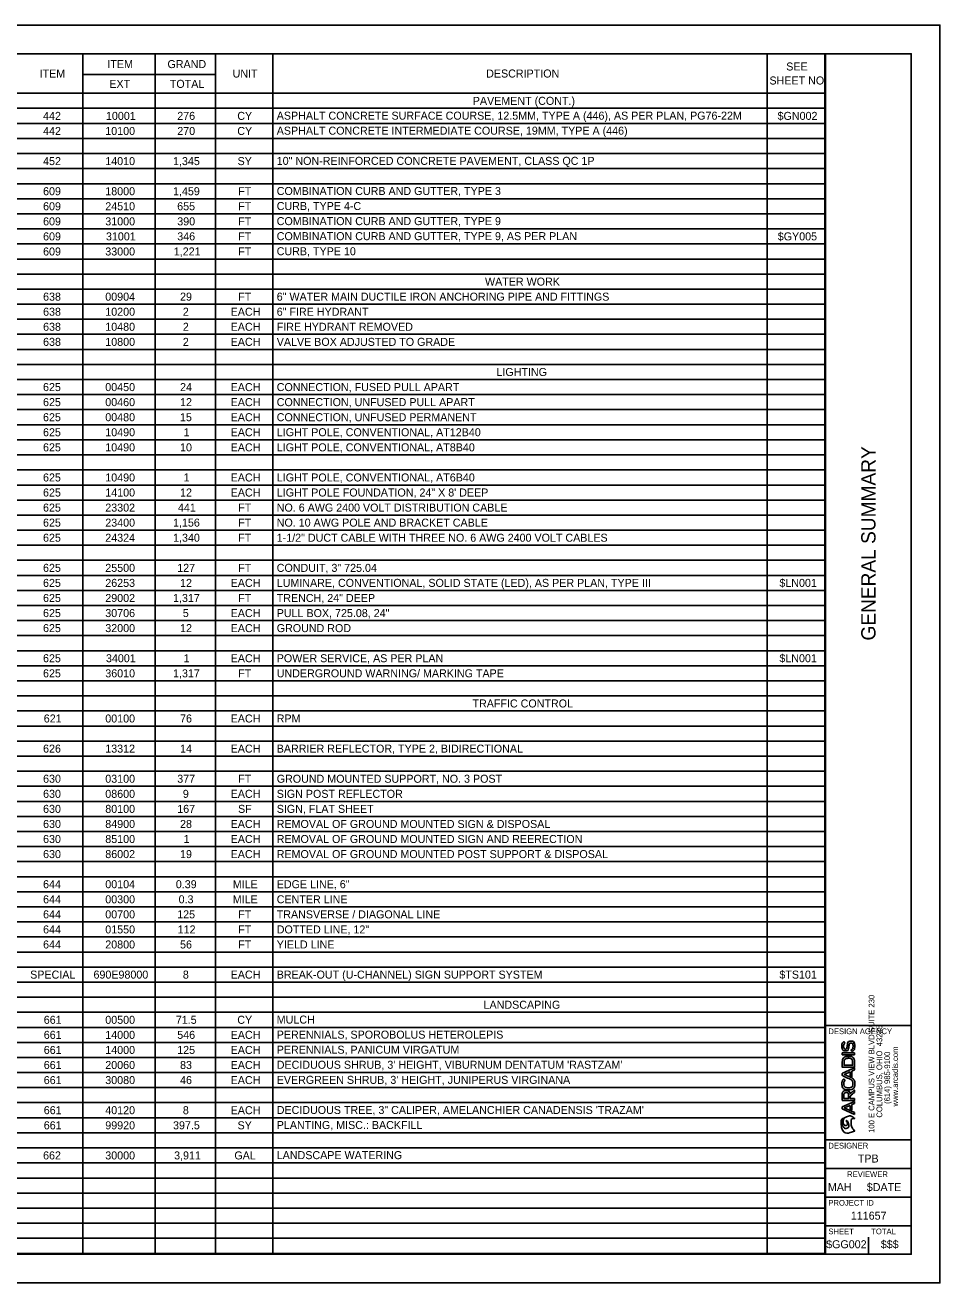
# Model space of a CAD drawing. Extents: x 0 to 34, y 0 to 22.
# Drawn here: x 18 to 34, y 0 to 22 of the extents above; entities that cross this region are included whole.
import ezdxf

# ---------------------------------------------------------------- set-up
doc = ezdxf.new("R2010")
doc.units = 0
for name, color, linetype in [('SH_Border', 7, 'Continuous'), ('SH_Cut_Line', 7, 'Continuous'), ('SH_Data', 7, 'Continuous'), ('SH_Text', 7, 'Continuous')]:
    doc.layers.add(name, color=color, linetype=linetype)

msp = doc.modelspace()

# ---------------------------------------------------------------- linework, layer by layer
at = {"layer": 'SH_Border'}
for p, q in [((32, 0.5), (32, 21.5)), ((32, 4.5), (33.5, 4.5)), ((32, 2.5), (33.5, 2.5)), ((32, 2), (33.5, 2)), ((32, 1.5), (33.5, 1.5)), ((32, 1), (33.5, 1))]:
    msp.add_line(p, q, dxfattribs=at)
msp.add_lwpolyline([(1.5, 21.5), (33.5, 21.5), (33.5, 0.5), (1.5, 0.5)], close=True, dxfattribs=at)
at = {"layer": 'SH_Cut_Line'}
msp.add_lwpolyline([(0, 0), (34, 0), (34, 22), (0, 22)], close=True, dxfattribs=at)
at = {"layer": 'SH_Data'}
for p, q in [((32.507, 4.022), (32.292, 4.022)), ((32.292, 4.022), (32.292, 3.988)), ((32.292, 3.988), (32.507, 3.988)), ((32.507, 3.988), (32.507, 4.022)), ((32.75, 3.5), (32.75, 3.5)), ((32.75, 3.5), (32.75, 3.5)), ((32.507, 3.175), (32.292, 3.079)), ((32.328, 3.06), (32.431, 3.105)), ((32.431, 3.105), (32.431, 3.034)), ((32.462, 3.119), (32.507, 3.139)), ((32.462, 3.02), (32.462, 3.119)), ((32.507, 3.139), (32.507, 3.175)), ((32.292, 3.079), (32.292, 3.041)), ((32.292, 3.041), (32.507, 2.945)), ((32.507, 2.981), (32.328, 3.06)), ((32.431, 3.034), (32.462, 3.02)), ((32.507, 2.945), (32.507, 2.981)), ((32.375, 0.675), (32.375, 0.675)), ((32.75, 0.5), (32.75, 0.8))]:
    msp.add_line(p, q, dxfattribs=at)
for points, degree in [([(32.34, 4.193), (32.325, 4.183), (32.316, 4.163), (32.316, 4.14), (32.316, 4.111), (32.328, 4.09), (32.348, 4.09), (32.369, 4.09), (32.375, 4.114), (32.379, 4.143), (32.385, 4.187), (32.398, 4.229), (32.446, 4.229), (32.494, 4.229), (32.512, 4.185), (32.512, 4.14), (32.512, 4.099), (32.5, 4.067), (32.463, 4.047), (32.463, 4.047), (32.446, 4.073), (32.446, 4.073), (32.472, 4.088), (32.482, 4.115), (32.482, 4.14), (32.482, 4.166), (32.473, 4.195), (32.446, 4.195), (32.422, 4.195), (32.414, 4.17), (32.41, 4.14), (32.405, 4.097), (32.394, 4.056), (32.348, 4.056), (32.303, 4.056), (32.286, 4.1), (32.286, 4.139), (32.286, 4.17), (32.293, 4.201), (32.322, 4.22), (32.322, 4.22), (32.34, 4.193), (32.34, 4.193), (32.34, 4.193), (32.34, 4.193), (32.34, 4.193)], 3), ([(32.292, 3.772), (32.292, 3.772), (32.507, 3.772), (32.507, 3.772), (32.507, 3.772), (32.507, 3.854), (32.507, 3.854), (32.507, 3.929), (32.452, 3.963), (32.398, 3.962), (32.345, 3.961), (32.292, 3.927), (32.292, 3.854)], 3), ([(32.292, 3.664), (32.292, 3.664), (32.292, 3.626), (32.292, 3.626), (32.292, 3.626), (32.432, 3.563), (32.432, 3.563), (32.432, 3.563), (32.432, 3.563), (32.432, 3.563), (32.445, 3.557), (32.453, 3.549), (32.456, 3.547), (32.471, 3.532), (32.479, 3.51), (32.479, 3.49), (32.479, 3.434), (32.44, 3.411), (32.401, 3.41), (32.361, 3.41), (32.321, 3.435), (32.321, 3.49), (32.321, 3.51), (32.328, 3.53), (32.343, 3.545), (32.343, 3.545), (32.321, 3.569), (32.321, 3.569), (32.299, 3.547), (32.288, 3.519), (32.288, 3.49), (32.288, 3.413), (32.345, 3.376), (32.401, 3.376), (32.458, 3.376), (32.512, 3.412), (32.512, 3.49), (32.512, 3.52), (32.502, 3.549), (32.48, 3.571), (32.48, 3.571), (32.466, 3.584), (32.446, 3.593), (32.446, 3.593), (32.44, 3.596), (32.44, 3.596), (32.44, 3.596), (32.425, 3.602), (32.425, 3.602), (32.425, 3.602), (32.425, 3.602), (32.425, 3.602), (32.425, 3.602), (32.328, 3.645), (32.328, 3.645), (32.328, 3.645), (32.431, 3.69), (32.431, 3.69), (32.431, 3.69), (32.431, 3.619), (32.431, 3.619), (32.431, 3.619), (32.462, 3.605), (32.462, 3.605), (32.462, 3.605), (32.462, 3.704), (32.462, 3.704), (32.462, 3.704), (32.507, 3.724), (32.507, 3.724), (32.507, 3.724), (32.507, 3.76), (32.507, 3.76), (32.507, 3.76), (32.292, 3.664), (32.292, 3.664), (32.292, 3.664), (32.292, 3.664), (32.292, 3.664)], 3), ([(32.292, 3.854), (32.292, 3.854), (32.292, 3.772), (32.292, 3.772)], 2), ([(32.474, 3.806), (32.474, 3.806), (32.325, 3.806), (32.325, 3.806)], 2), ([(32.325, 3.806), (32.325, 3.806), (32.325, 3.854), (32.325, 3.854), (32.325, 3.905), (32.361, 3.927), (32.398, 3.928), (32.435, 3.929), (32.474, 3.906), (32.474, 3.854), (32.474, 3.854), (32.474, 3.806), (32.474, 3.806)], 3), ([(32.43, 3.305), (32.423, 3.348), (32.393, 3.364), (32.362, 3.364), (32.326, 3.364), (32.292, 3.337), (32.292, 3.288), (32.292, 3.254), (32.292, 3.221), (32.292, 3.187), (32.292, 3.187), (32.507, 3.187), (32.507, 3.187), (32.507, 3.187), (32.507, 3.222), (32.507, 3.222), (32.507, 3.222), (32.433, 3.222), (32.433, 3.222), (32.433, 3.222), (32.433, 3.267), (32.433, 3.267), (32.433, 3.267), (32.507, 3.333), (32.507, 3.333), (32.507, 3.333), (32.507, 3.373), (32.507, 3.373)], 3), ([(32.323, 3.288), (32.323, 3.316), (32.344, 3.329), (32.363, 3.329), (32.383, 3.329), (32.402, 3.316), (32.402, 3.287), (32.402, 3.287), (32.402, 3.222), (32.402, 3.222), (32.402, 3.222), (32.323, 3.222), (32.323, 3.222)], 3), ([(32.507, 3.373), (32.507, 3.373), (32.43, 3.305), (32.43, 3.305)], 2), ([(32.323, 3.222), (32.323, 3.222), (32.323, 3.288), (32.323, 3.288)], 2), ([(32.272, 2.786), (32.282, 2.575), (32.514, 2.656), (32.514, 2.656), (32.494, 2.674), (32.446, 2.734), (32.446, 2.817), (32.446, 2.817), (32.446, 2.817), (32.446, 2.818), (32.446, 2.858), (32.48, 2.881), (32.514, 2.872), (32.514, 2.872), (32.441, 2.935), (32.357, 2.9), (32.329, 2.888), (32.309, 2.857), (32.309, 2.821), (32.309, 2.808), (32.311, 2.795), (32.316, 2.782), (32.329, 2.752), (32.356, 2.748), (32.369, 2.754), (32.378, 2.759), (32.383, 2.768), (32.383, 2.777), (32.383, 2.779), (32.383, 2.781), (32.383, 2.782), (32.378, 2.813), (32.364, 2.826), (32.364, 2.833), (32.364, 2.834), (32.364, 2.835), (32.365, 2.835), (32.368, 2.84), (32.383, 2.836), (32.398, 2.796), (32.402, 2.787), (32.407, 2.769), (32.407, 2.752), (32.407, 2.732), (32.401, 2.712), (32.38, 2.706), (32.343, 2.693), (32.298, 2.738), (32.293, 2.804), (32.292, 2.807), (32.292, 2.812), (32.292, 2.815), (32.292, 2.849), (32.307, 2.873), (32.317, 2.885), (32.294, 2.871), (32.273, 2.842), (32.272, 2.796), (32.272, 2.796), (32.272, 2.792), (32.272, 2.786), (32.272, 2.786), (32.272, 2.786), (32.272, 2.786)], 3)]:
    msp.add_open_spline(points, degree=degree, dxfattribs=at)
at = {"layer": 'SH_Text'}
for p, q in [((1.5, 21.5), (31.987, 21.5)), ((19.008, 21.5), (19.008, 0.516)), ((20.276, 21.5), (20.276, 0.516)), ((21.331, 21.5), (21.331, 0.516)), ((22.335, 21.5), (22.335, 0.516)), ((30.982, 21.5), (30.982, 0.516)), ((31.987, 21.5), (31.987, 0.516)), ((19.008, 21.138), (21.331, 21.138)), ((1.5, 20.808), (31.987, 20.808)), ((1.5, 20.545), (31.987, 20.545)), ((1.5, 20.281), (31.987, 20.281)), ((1.5, 20.018), (31.987, 20.018)), ((1.5, 19.754), (31.987, 19.754)), ((1.5, 19.491), (31.987, 19.491)), ((1.5, 19.227), (31.987, 19.227)), ((1.5, 18.964), (31.987, 18.964)), ((1.5, 18.7), (31.987, 18.7)), ((1.5, 18.436), (31.987, 18.436)), ((1.5, 18.173), (31.987, 18.173)), ((1.5, 17.909), (31.987, 17.909)), ((1.5, 17.646), (31.987, 17.646)), ((1.5, 17.382), (31.987, 17.382)), ((1.5, 17.119), (31.987, 17.119)), ((1.5, 16.855), (31.987, 16.855)), ((1.5, 16.592), (31.987, 16.592)), ((1.5, 16.328), (31.987, 16.328)), ((1.5, 16.065), (31.987, 16.065)), ((1.5, 15.801), (31.987, 15.801)), ((1.5, 15.538), (31.987, 15.538)), ((1.5, 15.274), (31.987, 15.274)), ((1.5, 15.011), (31.987, 15.011)), ((1.5, 14.747), (31.987, 14.747)), ((1.5, 14.484), (31.987, 14.484)), ((1.5, 14.22), (31.987, 14.22)), ((1.5, 13.956), (31.987, 13.956)), ((1.5, 13.693), (31.987, 13.693)), ((1.5, 13.429), (31.987, 13.429)), ((1.5, 13.166), (31.987, 13.166)), ((1.5, 12.902), (31.987, 12.902)), ((1.5, 12.639), (31.987, 12.639)), ((1.5, 12.375), (31.987, 12.375)), ((1.5, 12.112), (31.987, 12.112)), ((1.5, 11.848), (31.987, 11.848)), ((1.5, 11.585), (31.987, 11.585)), ((1.5, 11.321), (31.987, 11.321)), ((1.5, 11.058), (31.987, 11.058)), ((1.5, 10.794), (31.987, 10.794)), ((1.5, 10.531), (31.987, 10.531)), ((1.5, 10.267), (31.987, 10.267)), ((1.5, 10.004), (31.987, 10.004)), ((1.5, 9.74), (31.987, 9.74)), ((1.5, 9.476), (31.987, 9.476)), ((1.5, 9.213), (31.987, 9.213)), ((1.5, 8.949), (31.987, 8.949)), ((1.5, 8.686), (31.987, 8.686)), ((1.5, 8.422), (31.987, 8.422)), ((1.5, 8.159), (31.987, 8.159)), ((1.5, 7.895), (31.987, 7.895)), ((1.5, 7.632), (31.987, 7.632)), ((1.5, 7.368), (31.987, 7.368)), ((1.5, 7.105), (31.987, 7.105)), ((1.5, 6.841), (31.987, 6.841)), ((1.5, 6.578), (31.987, 6.578)), ((1.5, 6.314), (31.987, 6.314)), ((1.5, 6.051), (31.987, 6.051)), ((1.5, 5.787), (31.987, 5.787)), ((1.5, 5.524), (31.987, 5.524)), ((1.5, 5.26), (31.987, 5.26)), ((1.5, 4.996), (31.987, 4.996)), ((1.5, 4.733), (31.987, 4.733)), ((1.5, 4.469), (31.987, 4.469)), ((1.5, 4.206), (31.987, 4.206)), ((1.5, 3.942), (31.987, 3.942)), ((1.5, 3.679), (31.987, 3.679)), ((1.5, 3.415), (31.987, 3.415)), ((1.5, 3.152), (31.987, 3.152)), ((1.5, 2.888), (31.987, 2.888)), ((1.5, 2.625), (31.987, 2.625)), ((1.5, 2.361), (31.987, 2.361)), ((1.5, 2.098), (31.987, 2.098)), ((1.5, 1.834), (31.987, 1.834)), ((1.5, 1.571), (31.987, 1.571)), ((1.5, 1.307), (31.987, 1.307)), ((1.5, 1.044), (31.987, 1.044)), ((1.5, 0.78), (31.987, 0.78)), ((1.5, 0.516), (31.987, 0.516))]:
    msp.add_line(p, q, dxfattribs=at)

# ---------------------------------------------------------------- texts
at = {"layer": 'SH_Data'}
for s, height, p in [('GENERAL SUMMARY', 0.25, (32.875, 11.235)), ('100 E CAMPUS VIEW BLVD SUITE 230', 0.1, (32.855, 2.623)), ('COLUMBUS, OHIO  43235', 0.1, (32.992, 2.89)), ('(614) 985-9100', 0.1, (33.13, 3.13)), ('www.arcadis.com', 0.1, (33.268, 3.085))]:
    msp.add_text(s, height=height, rotation=90, dxfattribs=at).set_placement(p)
for s, height, p in [('DESIGN AGENCY', 0.1, (32.05, 4.35)), ('DESIGNER', 0.1, (32.05, 2.35)), ('TPB', 0.14, (32.565, 2.105)), ('REVIEWER', 0.1, (32.378, 1.85)), ('MAH', 0.14, (32.041, 1.605)), ('$DATE', 0.14, (32.722, 1.605)), ('PROJECT ID', 0.1, (32.05, 1.35)), ('111657', 0.14, (32.443, 1.105)), ('SHEET', 0.1, (32.05, 0.85)), ('TOTAL', 0.1, (32.8, 0.85)), ('$GG002', 0.14, (32.011, 0.605)), ('$$$', 0.14, (32.967, 0.605))]:
    msp.add_text(s, height=height, dxfattribs=at).set_placement(p)
at = {"layer": 'SH_Text'}
for s, p in [('ITEM', (19.439, 21.249)), ('GRAND', (20.49, 21.249)), ('SEE ', (31.313, 21.207)), ('ITEM', (18.253, 21.084)), ('UNIT', (21.629, 21.084)), ('DESCRIPTION', (26.064, 21.084)), ('EXT', (19.473, 20.903)), ('TOTAL', (20.531, 20.903)), ('SHEET NO.', (31.02, 20.962)), ('PAVEMENT (CONT.)', (25.83, 20.606)), ('442', (18.314, 20.343)), ('10001', (19.414, 20.343)), ('276', (20.661, 20.343)), ('CY', (21.711, 20.343)), ('ASPHALT CONCRETE SURFACE COURSE, 12.5MM, TYPE A (446), AS PER PLAN, PG76-22M', (22.401, 20.347)), ('$GN002', (31.162, 20.343)), ('442', (18.314, 20.079)), ('10100', (19.402, 20.079)), ('270', (20.661, 20.079)), ('CY', (21.711, 20.079)), ('ASPHALT CONCRETE INTERMEDIATE COURSE, 19MM, TYPE A (446)', (22.401, 20.084)), ('452', (18.314, 19.552)), ('14010', (19.402, 19.552)), ('1,345', (20.587, 19.552)), ('SY', (21.716, 19.552)), ('10" NON-REINFORCED CONCRETE PAVEMENT, CLASS QC 1P', (22.401, 19.556)), ('609', (18.314, 19.025)), ('18000', (19.402, 19.025)), ('1,459', (20.587, 19.025)), ('FT', (21.727, 19.025)), ('COMBINATION CURB AND GUTTER, TYPE 3', (22.401, 19.029)), ('609', (18.314, 18.762)), ('24510', (19.402, 18.762)), ('655', (20.66, 18.762)), ('FT', (21.727, 18.762)), ('CURB, TYPE 4-C', (22.401, 18.766)), ('609', (18.314, 18.498)), ('31000', (19.402, 18.498)), ('390', (20.661, 18.498)), ('FT', (21.727, 18.498)), ('COMBINATION CURB AND GUTTER, TYPE 9', (22.401, 18.502)), ('609', (18.314, 18.235)), ('31001', (19.414, 18.235)), ('346', (20.661, 18.235)), ('FT', (21.727, 18.235)), ('COMBINATION CURB AND GUTTER, TYPE 9, AS PER PLAN', (22.401, 18.239)), ('$GY005', (31.165, 18.235)), ('609', (18.314, 17.971)), ('33000', (19.402, 17.971)), ('1,221', (20.6, 17.971)), ('FT', (21.727, 17.971)), ('CURB, TYPE 10', (22.401, 17.975)), ('WATER WORK', (26.044, 17.444)), ('638', (18.314, 17.181)), ('00904', (19.402, 17.181)), ('29', (20.71, 17.181)), ('FT', (21.727, 17.181)), ('6" WATER MAIN DUCTILE IRON ANCHORING PIPE AND FITTINGS', (22.401, 17.181)), ('638', (18.314, 16.917)), ('10200', (19.402, 16.917)), ('2', (20.759, 16.917)), ('EACH', (21.595, 16.917)), ('6" FIRE HYDRANT', (22.401, 16.917)), ('638', (18.314, 16.654)), ('10480', (19.402, 16.654)), ('2', (20.759, 16.654)), ('EACH', (21.595, 16.654)), ('FIRE HYDRANT REMOVED', (22.401, 16.654)), ('638', (18.314, 16.39)), ('10800', (19.402, 16.39)), ('2', (20.759, 16.39)), ('EACH', (21.595, 16.39)), ('VALVE BOX ADJUSTED TO GRADE', (22.401, 16.39)), ('LIGHTING', (26.244, 15.863)), ('625', (18.313, 15.599)), ('00450', (19.402, 15.599)), ('24', (20.71, 15.599)), ('EACH', (21.595, 15.599)), ('CONNECTION, FUSED PULL APART', (22.401, 15.599)), ('625', (18.313, 15.336)), ('00460', (19.402, 15.336)), ('12', (20.71, 15.336)), ('EACH', (21.595, 15.336)), ('CONNECTION, UNFUSED PULL APART', (22.401, 15.336)), ('625', (18.313, 15.072)), ('00480', (19.402, 15.072)), ('15', (20.709, 15.072)), ('EACH', (21.595, 15.072)), ('CONNECTION, UNFUSED PERMANENT', (22.401, 15.072)), ('625', (18.313, 14.809)), ('10490', (19.402, 14.809)), ('1', (20.771, 14.809)), ('EACH', (21.595, 14.809)), ('LIGHT POLE, CONVENTIONAL, AT12B40', (22.401, 14.809)), ('625', (18.313, 14.545)), ('10490', (19.402, 14.545)), ('10', (20.71, 14.545)), ('EACH', (21.595, 14.545)), ('LIGHT POLE, CONVENTIONAL, AT8B40', (22.401, 14.545)), ('625', (18.313, 14.018)), ('10490', (19.402, 14.018)), ('1', (20.771, 14.018)), ('EACH', (21.595, 14.018)), ('LIGHT POLE, CONVENTIONAL, AT6B40', (22.401, 14.018)), ('625', (18.313, 13.755)), ('14100', (19.402, 13.755)), ('12', (20.71, 13.755)), ('EACH', (21.595, 13.755)), ('LIGHT POLE FOUNDATION, 24" X 8\' DEEP', (22.401, 13.755)), ('625', (18.313, 13.491)), ('23302', (19.402, 13.491)), ('441', (20.673, 13.491)), ('FT', (21.727, 13.491)), ('NO. 6 AWG 2400 VOLT DISTRIBUTION CABLE', (22.401, 13.491)), ('625', (18.313, 13.228)), ('23400', (19.402, 13.228)), ('1,156', (20.587, 13.228)), ('FT', (21.727, 13.228)), ('NO. 10 AWG POLE AND BRACKET CABLE', (22.401, 13.228)), ('625', (18.313, 12.964)), ('24324', (19.402, 12.964)), ('1,340', (20.588, 12.964)), ('FT', (21.727, 12.964)), ('1-1/2" DUCT CABLE WITH THREE NO. 6 AWG 2400 VOLT CABLES', (22.401, 12.964)), ('625', (18.313, 12.437)), ('25500', (19.402, 12.437)), ('127', (20.661, 12.437)), ('FT', (21.727, 12.437)), ('CONDUIT, 3" 725.04', (22.401, 12.437)), ('LUMINARE, CONVENTIONAL, SOLID STATE (LED), AS PER PLAN, TYPE III', (22.401, 12.174)), ('$LN001', (31.193, 12.174)), ('625', (18.313, 12.174)), ('26253', (19.402, 12.174)), ('12', (20.71, 12.174)), ('EACH', (21.595, 12.174)), ('625', (18.313, 11.91)), ('29002', (19.402, 11.91)), ('1,317', (20.587, 11.91)), ('FT', (21.727, 11.91)), ('TRENCH, 24" DEEP', (22.401, 11.91)), ('625', (18.313, 11.646)), ('30706', (19.402, 11.646)), ('5', (20.758, 11.646)), ('EACH', (21.595, 11.646)), ('PULL BOX, 725.08, 24"', (22.401, 11.646)), ('625', (18.313, 11.383)), ('32000', (19.402, 11.383)), ('12', (20.71, 11.383)), ('EACH', (21.595, 11.383)), ('GROUND ROD', (22.401, 11.383)), ('$LN001', (31.193, 10.856)), ('625', (18.313, 10.856)), ('34001', (19.414, 10.856)), ('1', (20.771, 10.856)), ('EACH', (21.595, 10.856)), ('POWER SERVICE, AS PER PLAN', (22.401, 10.856)), ('625', (18.313, 10.592)), ('36010', (19.402, 10.592)), ('1,317', (20.587, 10.592)), ('FT', (21.727, 10.592)), ('UNDERGROUND WARNING/ MARKING TAPE', (22.401, 10.592)), ('TRAFFIC CONTROL', (25.825, 10.065)), ('621', (18.326, 9.802)), ('00100', (19.402, 9.802)), ('76', (20.71, 9.802)), ('EACH', (21.595, 9.802)), ('RPM', (22.401, 9.802)), ('626', (18.314, 9.275)), ('13312', (19.402, 9.275)), ('14', (20.71, 9.275)), ('EACH', (21.595, 9.275)), ('BARRIER REFLECTOR, TYPE 2, BIDIRECTIONAL', (22.401, 9.275)), ('630', (18.314, 8.748)), ('03100', (19.402, 8.748)), ('377', (20.661, 8.748)), ('FT', (21.727, 8.748)), ('GROUND MOUNTED SUPPORT, NO. 3 POST', (22.401, 8.748)), ('630', (18.314, 8.484)), ('08600', (19.402, 8.484)), ('9', (20.759, 8.484)), ('EACH', (21.595, 8.484)), ('SIGN POST REFLECTOR', (22.401, 8.484)), ('630', (18.314, 8.221)), ('80100', (19.402, 8.221)), ('167', (20.661, 8.221)), ('SF', (21.724, 8.221)), ('SIGN, FLAT SHEET', (22.401, 8.221)), ('630', (18.314, 7.957)), ('84900', (19.402, 7.957)), ('28', (20.71, 7.957)), ('EACH', (21.595, 7.957)), ('REMOVAL OF GROUND MOUNTED SIGN & DISPOSAL', (22.401, 7.957)), ('630', (18.314, 7.694)), ('85100', (19.402, 7.694)), ('1', (20.771, 7.694)), ('EACH', (21.595, 7.694)), ('REMOVAL OF GROUND MOUNTED SIGN AND REERECTION', (22.401, 7.694)), ('630', (18.314, 7.43)), ('86002', (19.402, 7.43)), ('19', (20.71, 7.43)), ('EACH', (21.595, 7.43)), ('REMOVAL OF GROUND MOUNTED POST SUPPORT & DISPOSAL', (22.401, 7.43)), ('644', (18.314, 6.903)), ('00104', (19.402, 6.903)), ('0.39', (20.636, 6.903)), ('MILE', (21.632, 6.903)), ('EDGE LINE, 6"', (22.401, 6.903)), ('644', (18.314, 6.639)), ('00300', (19.402, 6.639)), ('0.3', (20.685, 6.639)), ('MILE', (21.632, 6.639)), ('CENTER LINE', (22.401, 6.639)), ('644', (18.314, 6.376)), ('00700', (19.402, 6.376)), ('125', (20.66, 6.376)), ('FT', (21.727, 6.376)), ('TRANSVERSE / DIAGONAL LINE', (22.401, 6.376)), ('644', (18.314, 6.112)), ('01550', (19.402, 6.112)), ('112', (20.668, 6.112)), ('FT', (21.727, 6.112)), ('DOTTED LINE, 12"', (22.401, 6.112)), ('644', (18.314, 5.849)), ('20800', (19.402, 5.849)), ('56', (20.71, 5.849)), ('FT', (21.727, 5.849)), ('YIELD LINE', (22.401, 5.849)), ('SPECIAL', (18.088, 5.322)), ('690E98000', (19.196, 5.322)), ('8', (20.759, 5.322)), ('EACH', (21.595, 5.322)), ('BREAK-OUT (U-CHANNEL) SIGN SUPPORT SYSTEM', (22.401, 5.322)), ('$TS101', (31.193, 5.322)), ('LANDSCAPING', (26.019, 4.795)), ('661', (18.326, 4.531)), ('00500', (19.402, 4.531)), ('71.5', (20.636, 4.531)), ('CY', (21.711, 4.531)), ('MULCH', (22.401, 4.535)), ('661', (18.326, 4.268)), ('14000', (19.402, 4.268)), ('546', (20.661, 4.268)), ('EACH', (21.595, 4.268)), ('PERENNIALS, SPOROBOLUS HETEROLEPIS', (22.401, 4.272)), ('661', (18.326, 4.004)), ('14000', (19.402, 4.004)), ('125', (20.66, 4.004)), ('EACH', (21.595, 4.004)), ('PERENNIALS, PANICUM VIRGATUM', (22.401, 4.008)), ('661', (18.326, 3.741)), ('20060', (19.402, 3.741)), ('83', (20.71, 3.741)), ('EACH', (21.595, 3.741)), ("DECIDUOUS SHRUB, 3' HEIGHT, VIBURNUM DENTATUM 'RASTZAM'", (22.401, 3.745)), ('661', (18.326, 3.477)), ('30080', (19.402, 3.477)), ('46', (20.71, 3.477)), ('EACH', (21.595, 3.477)), ("EVERGREEN SHRUB, 3' HEIGHT, JUNIPERUS VIRGINANA", (22.401, 3.481)), ('661', (18.326, 2.95)), ('40120', (19.402, 2.95)), ('8', (20.759, 2.95)), ('EACH', (21.595, 2.95)), ('DECIDUOUS TREE, 3" CALIPER, AMELANCHIER CANADENSIS \'TRAZAM\'', (22.401, 2.954)), ('661', (18.326, 2.686)), ('99920', (19.402, 2.686)), ('397.5', (20.587, 2.686)), ('SY', (21.716, 2.686)), ('PLANTING, MISC.: BACKFILL', (22.401, 2.691)), ('662', (18.314, 2.159)), ('30000', (19.402, 2.159)), ('3,911', (20.606, 2.159)), ('GAL', (21.66, 2.159)), ('LANDSCAPE WATERING', (22.401, 2.164))]:
    msp.add_text(s, height=0.14, dxfattribs=at).set_placement(p)

doc.saveas('drawing.dxf')
